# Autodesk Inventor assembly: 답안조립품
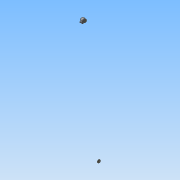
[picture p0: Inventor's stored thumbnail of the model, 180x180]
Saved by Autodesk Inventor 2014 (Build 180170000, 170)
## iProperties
Created: 2016-01
Part Number: 답안조립품
Document SubType Name: Assembly
Designer: Administrator
Author: Administrator
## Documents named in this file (16)
- C:\Users\Administrator\Desktop\460106V1042\답안조립품.iam
- C:\Users\Administrator\Desktop\460106V1042\1-본체.ipt
- C:\Users\Administrator\Desktop\460106V1042\뒤커버.ipt
- C:\Users\Administrator\Desktop\460106V1042\베어링 6203.ipt
- C:\Users\Administrator\Desktop\460106V1042\볼트 M3 x 8.ipt
- C:\Users\Administrator\Desktop\460106V1042\축.ipt
- C:\Users\Administrator\Desktop\460106V1042\부시1.ipt
- C:\Users\Administrator\Desktop\460106V1042\키 - 6 x 6 x 22.ipt
- C:\Users\Administrator\Desktop\460106V1042\키 - 5 x 5 x 18.ipt
- C:\Users\Administrator\Desktop\460106V1042\앞커버.ipt
- C:\Users\Administrator\Desktop\460106V1042\오일씰 28 40 8.ipt
- C:\Users\Administrator\Desktop\460106V1042\부시2.ipt
- C:\Users\Administrator\Desktop\460106V1042\V-벨트풀리.ipt
- C:\Users\Administrator\Desktop\460106V1042\멈춤나사 - M4x10.ipt
- C:\Users\Administrator\Desktop\460106V1042\스퍼기어.ipt
- C:\Users\Administrator\Desktop\460106V1042\볼트 M3 x 10.ipt
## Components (11 placed, 4 different names)
1. 1-본체:1 — 플러쉬:1
2. V-벨트풀리:1
3. V-벨트풀리:2 — 플러쉬:3
4. ISO 4762 M3 x 8:1
5. ISO 4762 M3 x 8:2
6. ISO 4762 M3 x 8:3
7. ISO 4762 M3 x 8:4
8. ISO 4762 M3 x 10:1
9. ISO 4762 M3 x 10:2
10. ISO 4762 M3 x 10:3
11. ISO 4762 M3 x 10:4
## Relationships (2: Flush 2)
- 플러쉬:1 [Flush]: 1-본체:1
- 플러쉬:3 [Flush]: V-벨트풀리:2
